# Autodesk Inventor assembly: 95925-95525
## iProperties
Author: Administrator
Created: 2002-04
Part Number: 95925-95525
Document SubType Name: Assembly
Designer: Administrator
Control State: 0
Master: False
Checked Out: False
PropertySet Name: Design Tracking Control
Shininess: 64.0
Angle Display Precision: 2
Document Length Units: 11272
Document Angle Units: 11286
Document Time Units: 11279
Document Mass Units: 11290
Document Length Units Precision: 3
Document Angle Units Precision: 2
Compacted: True
PropertySet Name: _Private Model Information
Density: 0.0
Volumn: 0.0
Area: 0.0
PropertySet Name: Model Information
